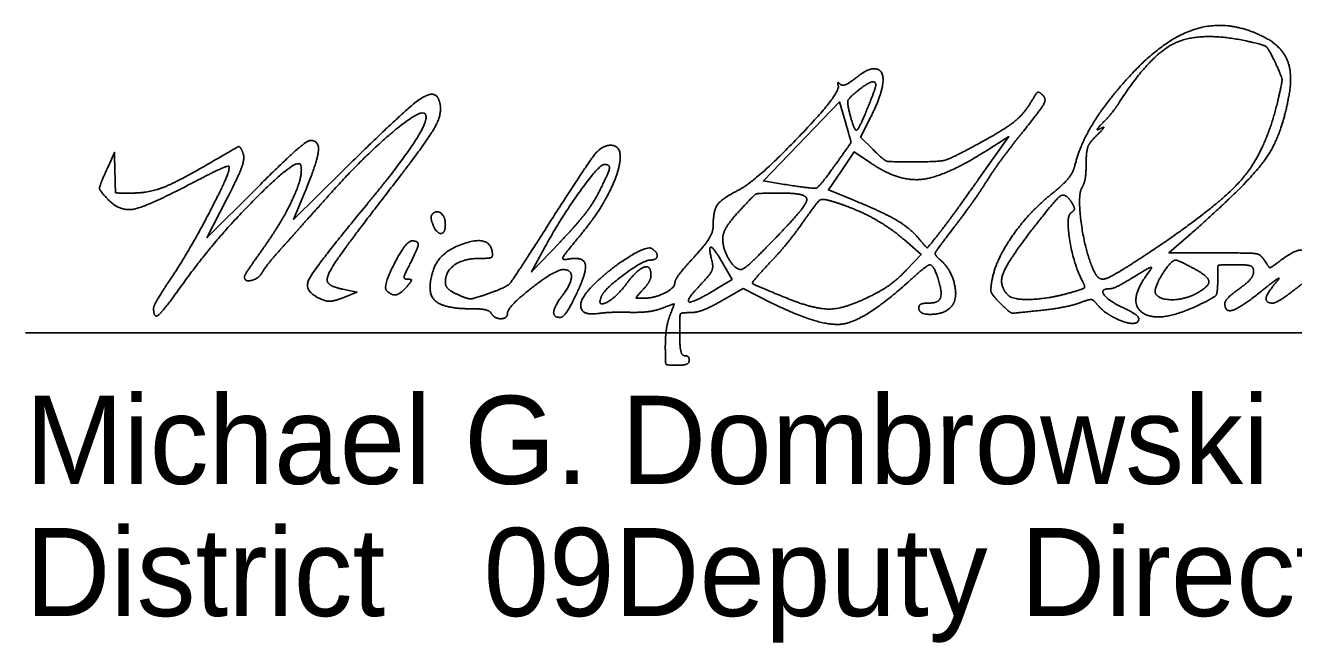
# Model space of a CAD drawing. Extents: x 0 to 40.8, y 0 to 22.
# Drawn here: x 24.5 to 26.515, y 8.324 to 9.305 of the extents above; entities that cross this region are included whole.
import ezdxf

# ---------------------------------------------------------------- set-up
doc = ezdxf.new("R2010")
doc.units = 0
doc.layers.add('SH_Data', color=7, linetype='Continuous')
doc.layers.add('SH_Text', color=7, linetype='Continuous')

msp = doc.modelspace()

# ---------------------------------------------------------------- linework, layer by layer
at = {"layer": 'SH_Data'}
msp.add_line((24.5, 8.816), (28, 8.816), dxfattribs=at)
at = {"layer": 'SH_Text'}
for p, q in [((25.1473, 8.989), (25.1473, 8.989)), ((25.074, 8.8832), (25.074, 8.8832)), ((24.7038, 8.8549), (24.7038, 8.8549))]:
    msp.add_line(p, q, dxfattribs=at)
for points in [[(25.7032, 9.0524), (25.6728, 9.0573), (25.7937, 9.183), (25.8032, 9.1508)], [(25.8471, 9.1073), (25.8273, 9.1272), (25.8431, 9.1583)], [(26.0277, 9.1057), (26.0627, 9.128), (26.016, 9.0619)], [(24.6314, 9.0799), (24.6418, 9.1027), (24.6424, 9.0704)], [(25.8166, 9.0266), (25.7763, 9.043), (25.7968, 9.0734), (25.8172, 9.1037), (25.8431, 9.0861)], [(24.9443, 9.0398), (24.9263, 8.9963), (25.0032, 9.0723)], [(24.8197, 9.0278), (24.7885, 8.9672), (24.866, 9.0444)], [(26.3894, 8.9431), (26.3173, 8.9431), (26.352, 8.9735)], [(25.3498, 8.9603), (25.3044, 8.9127), (25.3252, 8.9513)], [(25.897, 8.9636), (25.9236, 8.9406), (25.9008, 8.9165)], [(25.6099, 8.9238), (25.623, 8.9008), (25.5985, 8.8859)], [(25.0047, 8.8854), (25.0268, 8.8809), (25.006, 8.8723)], [(25.6073, 8.8673), (25.6406, 8.8863), (25.6864, 8.8634)]]:
    msp.add_lwpolyline(points, dxfattribs=at)
for points in [[(26.467, 9.2868), (26.4102, 9.3152), (26.3049, 9.281), (26.2472, 9.2155)], [(26.239, 9.1831), (26.2861, 9.2567), (26.3666, 9.2955), (26.44, 9.2798)], [(26.44, 9.2798), (26.4676, 9.2739), (26.4755, 9.2681), (26.486, 9.246)], [(26.5088, 9.1977), (26.5142, 9.2305), (26.4942, 9.2732), (26.467, 9.2868)], [(25.8487, 9.2357), (25.843, 9.2357), (25.8297, 9.2289), (25.8193, 9.2207)], [(25.8431, 9.1583), (25.8614, 9.1942), (25.8644, 9.2357), (25.8487, 9.2357)], [(26.486, 9.246), (26.4968, 9.2233), (26.4973, 9.2138), (26.4897, 9.1819)], [(25.7948, 9.2112), (25.7918, 9.2142), (25.7905, 9.213), (25.7919, 9.2084)], [(25.8193, 9.2207), (25.8088, 9.2125), (25.7978, 9.2082), (25.7948, 9.2112)], [(25.8213, 9.1994), (25.8372, 9.2123), (25.8514, 9.2169), (25.8514, 9.2092)], [(26.2472, 9.2155), (26.2136, 9.1773), (26.1756, 9.1135), (26.168, 9.0824)], [(25.0032, 9.0723), (25.0977, 9.1656), (25.1501, 9.2045), (25.157, 9.1864)], [(25.7919, 9.2084), (25.7955, 9.1967), (25.6624, 9.0578), (25.6332, 9.0428)], [(25.8099, 9.1652), (25.8058, 9.1813), (25.8084, 9.189), (25.8213, 9.1994)], [(25.8514, 9.2092), (25.8514, 9.2072), (25.8459, 9.1918), (25.8392, 9.175)], [(26.0861, 9.1365), (26.114, 9.1712), (26.1229, 9.1876), (26.1171, 9.1934)], [(26.1171, 9.1934), (26.1113, 9.1991), (26.1067, 9.1976), (26.1013, 9.1881)], [(26.352, 8.9735), (26.4443, 9.0542), (26.4977, 9.1305), (26.5088, 9.1977)], [(25.157, 9.1864), (25.164, 9.1684), (25.1419, 9.1251), (25.0952, 9.0647)], [(25.8392, 9.175), (25.8249, 9.1392), (25.8171, 9.1366), (25.8099, 9.1652)], [(26.1013, 9.1881), (26.0882, 9.1649), (26.055, 9.1381), (26.0075, 9.1126)], [(26.2124, 9.1499), (26.2208, 9.1584), (26.2328, 9.1733), (26.239, 9.1831)], [(26.4897, 9.1819), (26.4708, 9.1033), (26.3943, 9.0153), (26.278, 8.9383)], [(25.135, 9.1642), (25.1273, 9.1719), (25.0363, 9.0949), (24.9838, 9.0362)], [(25.0419, 9.0191), (25.0961, 9.0845), (25.1425, 9.1568), (25.135, 9.1642)], [(25.8032, 9.1508), (25.8124, 9.1198), (25.8118, 9.1174), (25.7879, 9.0841)], [(26.0278, 9.0572), (26.0383, 9.0739), (26.0646, 9.1096), (26.0861, 9.1365)], [(26.2029, 9.1301), (26.2123, 9.1392), (26.2149, 9.144), (26.2086, 9.1407)], [(26.2086, 9.1407), (26.2024, 9.1374), (26.2041, 9.1415), (26.2124, 9.1499)], [(24.804, 9.0921), (24.8369, 9.1115), (24.8417, 9.1125), (24.846, 9.1012)], [(24.866, 9.0444), (24.9086, 9.0869), (24.9477, 9.1217), (24.9529, 9.1217)], [(24.9529, 9.1217), (24.9675, 9.1217), (24.9639, 9.0875), (24.9443, 9.0398)], [(25.43, 9.1141), (25.416, 9.1141), (25.3902, 9.0805), (25.3225, 8.9744)], [(25.4251, 9.0342), (25.4438, 9.0698), (25.4466, 9.1141), (25.43, 9.1141)], [(26.0075, 9.1126), (25.9701, 9.0926), (25.9529, 9.0879), (25.9143, 9.0877)], [(26.1857, 9.0853), (26.1858, 9.1044), (26.1913, 9.1188), (26.2029, 9.1301)], [(24.6687, 9.0381), (24.6965, 9.0381), (24.7456, 9.0577), (24.804, 9.0921)], [(24.846, 9.1012), (24.849, 9.0935), (24.8386, 9.0646), (24.8197, 9.0278)], [(25.8431, 9.0861), (25.8873, 9.0559), (25.9615, 9.0638), (26.0277, 9.1057)], [(25.9143, 9.0877), (25.8733, 9.0875), (25.8644, 9.0901), (25.8471, 9.1073)], [(24.6329, 9.0265), (24.6178, 9.0416), (24.6176, 9.0497), (24.6314, 9.0799)], [(24.6424, 9.0704), (24.643, 9.0389), (24.6437, 9.0381), (24.6687, 9.0381)], [(24.7313, 8.9024), (24.761, 8.9466), (24.8281, 9.0759), (24.8236, 9.0805)], [(24.938, 9.0816), (24.9348, 9.0984), (24.8011, 8.965), (24.7516, 8.8956)], [(24.8236, 9.0805), (24.8221, 9.082), (24.7952, 9.0698), (24.7638, 9.0534)], [(24.8747, 8.9457), (24.9076, 8.9915), (24.9414, 9.0641), (24.938, 9.0816)], [(25.3252, 8.9513), (25.3497, 8.9967), (25.4119, 9.0835), (25.4201, 9.0836)], [(25.4201, 9.0836), (25.4296, 9.0837), (25.4266, 9.0694), (25.4105, 9.0379)], [(25.7879, 9.0841), (25.7619, 9.0478), (25.753, 9.0445), (25.7032, 9.0524)], [(26.168, 9.0824), (26.1653, 9.0713), (26.1492, 9.0512), (26.1323, 9.0378)], [(26.1794, 9.0473), (26.1828, 9.0527), (26.1857, 9.0698), (26.1857, 9.0853)], [(24.7638, 9.0534), (24.6945, 9.0171), (24.6512, 9.0082), (24.6329, 9.0265)], [(25.0952, 9.0647), (25.0175, 8.9643), (24.9771, 8.906), (24.9798, 8.898)], [(26.016, 9.0619), (25.9903, 9.0256), (25.9619, 8.9866), (25.9529, 8.9752)], [(25.9758, 8.9838), (25.9939, 9.0074), (26.0173, 9.0404), (26.0278, 9.0572)], [(24.9838, 9.0362), (24.9531, 9.0019), (24.9178, 8.9623), (24.9052, 8.9482)], [(25.4105, 9.0379), (25.4021, 9.0213), (25.3748, 8.9864), (25.3498, 8.9603)], [(25.3786, 8.9672), (25.3954, 8.9874), (25.4163, 9.0175), (25.4251, 9.0342)], [(25.6332, 9.0428), (25.6065, 9.0292), (25.593, 9.0099), (25.593, 8.9852)], [(25.6345, 9.0096), (25.658, 9.0352), (25.6645, 9.0381), (25.6986, 9.0381)], [(25.7413, 9.0303), (25.744, 9.026), (25.7231, 8.9987), (25.6949, 8.9695)], [(25.6986, 9.0381), (25.7195, 9.0381), (25.7387, 9.0346), (25.7413, 9.0303)], [(26.1323, 9.0378), (26.0961, 9.0092), (26.043, 8.9339), (26.0367, 8.9023)], [(26.0927, 8.9705), (26.1354, 9.0265), (26.1527, 9.0394), (26.1628, 9.0231)], [(26.1947, 8.9222), (26.1824, 8.9537), (26.1723, 9.0362), (26.1794, 9.0473)], [(24.9743, 8.8679), (24.9416, 8.8804), (24.9586, 8.9185), (25.0419, 9.0191)], [(25.6083, 8.9657), (25.6083, 8.9741), (25.6201, 8.9939), (25.6345, 9.0096)], [(25.7376, 8.9945), (25.7578, 9.0233), (25.7661, 9.0297), (25.7787, 9.026)], [(25.7787, 9.026), (25.8144, 9.0155), (25.8721, 8.9851), (25.897, 8.9636)], [(25.9199, 8.9658), (25.9062, 8.9822), (25.8627, 9.0079), (25.8166, 9.0266)], [(26.1628, 9.0231), (26.1673, 9.016), (26.1669, 9.0101), (26.1619, 9.007)], [(25.1473, 8.989), (25.1448, 8.9955), (25.1447, 9.0026), (25.147, 9.005)], [(25.147, 9.005), (25.1536, 9.0116), (25.1674, 9.0003), (25.1674, 8.9882)], [(25.6853, 8.9298), (25.7002, 8.9455), (25.7237, 8.9746), (25.7376, 8.9945)], [(26.1619, 9.007), (26.1535, 9.0018), (26.1659, 8.9249), (26.1791, 8.8998)], [(25.1674, 8.9882), (25.1674, 8.9736), (25.1529, 8.9742), (25.1473, 8.989)], [(25.3225, 8.9744), (25.2749, 8.8998), (25.2649, 8.8886), (25.2375, 8.8789)], [(25.593, 8.9852), (25.593, 8.9765), (25.5794, 8.9545), (25.5626, 8.9364)], [(25.6949, 8.9695), (25.6668, 8.9403), (25.6411, 8.9165), (25.6378, 8.9165)], [(25.9529, 8.9752), (25.934, 8.9512), (25.9324, 8.9507), (25.9199, 8.9658)], [(25.9541, 8.9316), (25.9446, 8.9395), (25.9478, 8.9472), (25.9758, 8.9838)], [(26.0617, 8.8759), (26.0472, 8.8904), (26.059, 8.9263), (26.0927, 8.9705)], [(25.074, 8.8832), (25.0677, 8.8895), (25.1048, 8.9621), (25.1144, 8.9621)], [(25.1144, 8.9621), (25.125, 8.9621), (25.1236, 8.9496), (25.1102, 8.9237)], [(25.2416, 8.9462), (25.2364, 8.9712), (25.1574, 8.9447), (25.1479, 8.9148)], [(25.3612, 8.933), (25.352, 8.9313), (25.3573, 8.9418), (25.3786, 8.9672)], [(25.4953, 8.95), (25.488, 8.9545), (25.4309, 8.9193), (25.4045, 8.8939)], [(25.4931, 8.9317), (25.5033, 8.9317), (25.5048, 8.9441), (25.4953, 8.95)], [(25.5909, 8.9312), (25.585, 8.9541), (25.5949, 8.9502), (25.6099, 8.9238)], [(25.6378, 8.9165), (25.6279, 8.9165), (25.6082, 8.9493), (25.6083, 8.9657)], [(24.8482, 8.9051), (24.8482, 8.9071), (24.8602, 8.9254), (24.8747, 8.9457)], [(24.9052, 8.9482), (24.8927, 8.9342), (24.8797, 8.9179), (24.8764, 8.912)], [(25.1674, 8.8961), (25.1674, 8.9135), (25.1966, 8.9342), (25.221, 8.9342)], [(25.221, 8.9342), (25.238, 8.9342), (25.2434, 8.9374), (25.2416, 8.9462)], [(25.3744, 8.875), (25.3927, 8.9126), (25.3869, 8.9378), (25.3612, 8.933)], [(25.4153, 8.8736), (25.4201, 8.8854), (25.4822, 8.9317), (25.4931, 8.9317)], [(25.5626, 8.9364), (25.5459, 8.9182), (25.5322, 8.9), (25.5322, 8.8959)], [(25.5736, 8.8932), (25.5881, 8.9084), (25.5937, 8.9207), (25.5909, 8.9312)], [(25.7115, 8.8705), (25.6563, 8.8927), (25.6544, 8.8971), (25.6853, 8.9298)], [(25.9719, 8.8581), (25.9821, 8.8704), (25.9705, 8.918), (25.9541, 8.9316)], [(26.278, 8.9383), (26.2471, 8.918), (26.2176, 8.9013), (26.2124, 8.9013)], [(26.2961, 8.8783), (26.2922, 8.8847), (26.3205, 8.9317), (26.3282, 8.9317)], [(26.3282, 8.9317), (26.3298, 8.9317), (26.3411, 8.9265), (26.3534, 8.9201)], [(26.4695, 8.9306), (26.4631, 8.9407), (26.4482, 8.9431), (26.3894, 8.9431)], [(26.4981, 8.9334), (26.4791, 8.9193), (26.4767, 8.9191), (26.4695, 8.9306)], [(26.5325, 8.9274), (26.5395, 8.9457), (26.5194, 8.9491), (26.4981, 8.9334)], [(24.8764, 8.912), (24.8707, 8.9021), (24.8482, 8.8965), (24.8482, 8.9051)], [(25.1102, 8.9237), (25.1024, 8.9085), (25.1014, 8.9013), (25.1074, 8.9013)], [(25.1479, 8.9148), (25.1371, 8.8807), (25.1643, 8.8542), (25.2102, 8.8542)], [(25.2662, 8.8474), (25.2662, 8.8573), (25.342, 8.9165), (25.3546, 8.9165)], [(25.3546, 8.9165), (25.3682, 8.9165), (25.3675, 8.8938), (25.3534, 8.8751)], [(25.4942, 8.9076), (25.4942, 8.9242), (25.472, 8.9166), (25.4555, 8.8943)], [(25.9008, 8.9165), (25.8883, 8.9032), (25.865, 8.8856), (25.849, 8.8774)], [(25.9028, 8.8967), (25.9194, 8.9118), (25.9349, 8.9241), (25.9371, 8.9241)], [(25.9371, 8.9241), (25.9438, 8.9241), (25.958, 8.8773), (25.9535, 8.87)], [(26.2124, 8.9013), (26.2072, 8.9013), (26.1992, 8.9107), (26.1947, 8.9222)], [(26.2639, 8.9063), (26.2816, 8.9175), (26.2923, 8.9217), (26.2877, 8.9158)], [(26.2877, 8.9158), (26.2489, 8.8657), (26.3027, 8.8297), (26.3682, 8.8619)], [(26.3534, 8.9201), (26.3792, 8.9067), (26.3823, 8.8901), (26.3611, 8.8787)], [(26.3948, 8.8976), (26.3948, 8.9228), (26.3965, 8.9241), (26.429, 8.9241)], [(26.429, 8.9241), (26.4438, 8.9241), (26.4518, 8.9202), (26.4518, 8.9132)], [(26.4518, 8.9132), (26.4518, 8.9072), (26.4416, 8.895), (26.429, 8.8861)], [(24.7038, 8.8549), (24.7038, 8.8587), (24.7162, 8.88), (24.7313, 8.9024)], [(24.7516, 8.8956), (24.7204, 8.8519), (24.7038, 8.8377), (24.7038, 8.8549)], [(24.9798, 8.898), (24.9813, 8.8935), (24.9925, 8.8879), (25.0047, 8.8854)], [(25.1066, 8.8899), (25.0968, 8.878), (25.0822, 8.875), (25.074, 8.8832)], [(25.1074, 8.9013), (25.1136, 8.9013), (25.1134, 8.898), (25.1066, 8.8899)], [(25.187, 8.8768), (25.1762, 8.8817), (25.1674, 8.8904), (25.1674, 8.8961)], [(25.4045, 8.8939), (25.3808, 8.8712), (25.3844, 8.8433), (25.4106, 8.8468)], [(25.4555, 8.8943), (25.4393, 8.8724), (25.4083, 8.8564), (25.4153, 8.8736)], [(25.5322, 8.8959), (25.5322, 8.8872), (25.499, 8.8709), (25.4813, 8.8709)], [(25.4817, 8.8848), (25.4886, 8.8924), (25.4942, 8.9027), (25.4942, 8.9076)], [(25.5985, 8.8859), (25.5613, 8.8632), (25.5485, 8.867), (25.5736, 8.8932)], [(25.6864, 8.8634), (25.764, 8.8246), (25.8351, 8.8356), (25.9028, 8.8967)], [(26.0367, 8.9023), (26.0333, 8.8855), (26.0364, 8.8759), (26.0491, 8.8632)], [(26.1791, 8.8998), (26.1848, 8.8891), (26.1809, 8.8854), (26.1574, 8.8789)], [(26.2234, 8.8861), (26.228, 8.8861), (26.2462, 8.8952), (26.2639, 8.9063)], [(26.3682, 8.8619), (26.3898, 8.8725), (26.3948, 8.8793), (26.3948, 8.8976)], [(26.4662, 8.8838), (26.4855, 8.8993), (26.4952, 8.905), (26.4879, 8.8965)], [(26.4879, 8.8965), (26.4731, 8.8793), (26.4705, 8.8633), (26.4825, 8.8633)], [(26.4825, 8.8633), (26.4868, 8.8633), (26.5076, 8.877), (26.5287, 8.8937)], [(25.006, 8.8723), (24.9945, 8.8676), (24.9803, 8.8656), (24.9743, 8.8679)], [(25.2375, 8.8789), (25.213, 8.8702), (25.2024, 8.8698), (25.187, 8.8768)], [(25.3534, 8.8751), (25.3405, 8.8581), (25.3387, 8.8405), (25.3499, 8.8405)], [(25.3499, 8.8405), (25.3542, 8.8405), (25.3652, 8.856), (25.3744, 8.875)], [(25.4813, 8.8709), (25.4702, 8.8709), (25.4702, 8.8722), (25.4817, 8.8848)], [(25.849, 8.8774), (25.8058, 8.8551), (25.7559, 8.8526), (25.7115, 8.8705)], [(25.9535, 8.87), (25.9512, 8.8663), (25.9427, 8.8633), (25.9346, 8.8633)], [(26.1574, 8.8789), (26.1253, 8.87), (26.0694, 8.8682), (26.0617, 8.8759)], [(26.1761, 8.8639), (26.1904, 8.8693), (26.1975, 8.8685), (26.2039, 8.8606)], [(26.245, 8.8557), (26.2209, 8.867), (26.2074, 8.8861), (26.2234, 8.8861)], [(26.3611, 8.8787), (26.3425, 8.8688), (26.3022, 8.8685), (26.2961, 8.8783)], [(26.429, 8.8861), (26.4165, 8.8771), (26.4062, 8.8667), (26.4062, 8.8628)], [(26.4062, 8.8628), (26.4062, 8.8476), (26.4328, 8.8569), (26.4662, 8.8838)], [(25.2102, 8.8542), (25.2243, 8.8542), (25.2378, 8.8511), (25.2401, 8.8473)], [(25.4106, 8.8468), (25.4211, 8.8482), (25.4439, 8.849), (25.4614, 8.8486)], [(25.4614, 8.8486), (25.4788, 8.8483), (25.5018, 8.8513), (25.5124, 8.8553)], [(25.5124, 8.8553), (25.5307, 8.8623), (25.5313, 8.8617), (25.5243, 8.8435)], [(25.5398, 8.8139), (25.5398, 8.8442), (25.5417, 8.8481), (25.5569, 8.8482)], [(25.5569, 8.8482), (25.5663, 8.8482), (25.589, 8.8568), (25.6073, 8.8673)], [(25.9346, 8.8633), (25.9265, 8.8633), (25.9198, 8.8599), (25.9198, 8.8557)], [(25.9198, 8.8557), (25.9198, 8.8445), (25.9622, 8.8464), (25.9719, 8.8581)], [(26.0491, 8.8632), (26.0642, 8.8481), (26.0708, 8.8469), (26.1114, 8.8515)], [(26.1114, 8.8515), (26.1364, 8.8543), (26.1655, 8.8599), (26.1761, 8.8639)], [(26.2039, 8.8606), (26.2086, 8.8547), (26.2193, 8.8462), (26.2276, 8.8417)], [(26.2693, 8.8386), (26.2692, 8.8417), (26.2582, 8.8494), (26.245, 8.8557)], [(25.2401, 8.8473), (25.2456, 8.8384), (25.2662, 8.8385), (25.2662, 8.8474)], [(25.5243, 8.8435), (25.5203, 8.8329), (25.517, 8.8108), (25.517, 8.7944)], [(26.2276, 8.8417), (26.2452, 8.832), (26.2695, 8.8302), (26.2693, 8.8386)], [(25.5474, 8.7797), (25.5433, 8.7797), (25.5398, 8.7951), (25.5398, 8.8139)], [(25.517, 8.7944), (25.517, 8.7675), (25.519, 8.7645), (25.536, 8.7645)], [(25.536, 8.7645), (25.5465, 8.7645), (25.555, 8.7679), (25.555, 8.7721)], [(25.555, 8.7721), (25.555, 8.7763), (25.5516, 8.7797), (25.5474, 8.7797)]]:
    msp.add_open_spline(points, degree=2, dxfattribs=at)

# ---------------------------------------------------------------- texts
for s, p in [('Michael G. Dombrowski', (24.5, 8.576)), ('District       Deputy Director', (24.5, 8.366)), ('              09', (24.5, 8.366))]:
    msp.add_text(s, height=0.14, dxfattribs=at).set_placement(p)

doc.saveas('drawing.dxf')
